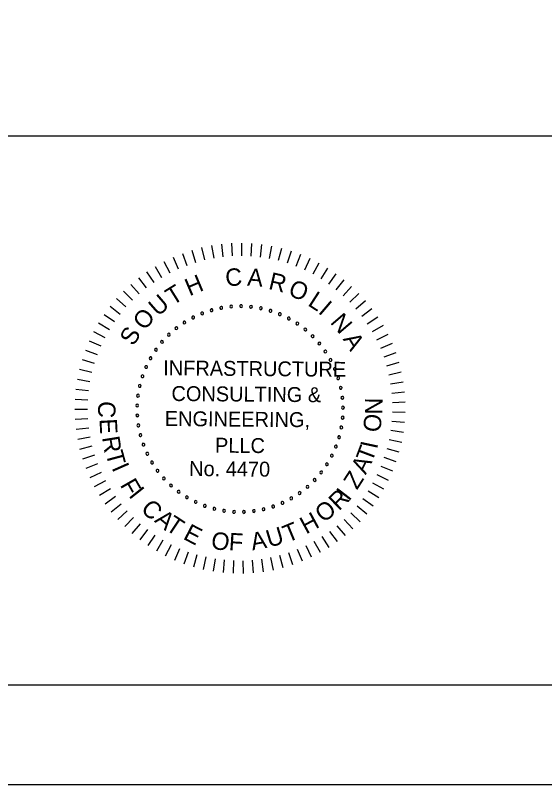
# Model space of a CAD drawing. Extents: x -133.1 to -97, y -1.7 to 20.6.
# Drawn here: x -107.934 to -105.282, y -1.691 to 2.163 of the extents above; entities that cross this region are included whole.
import ezdxf

# ---------------------------------------------------------------- set-up
doc = ezdxf.new("R2010")
doc.units = 0
for name, color, linetype in [('BR_BORDER LINES', 7, 'Continuous'), ('BR_TEXT', 7, 'Continuous'), ('Level 31', 7, 'Continuous')]:
    doc.layers.add(name, color=color, linetype=linetype)

msp = doc.modelspace()

# ---------------------------------------------------------------- linework, layer by layer
at = {"layer": 'BR_BORDER LINES'}
for p, q in [((-110.5071, 1.5591), (-105.1419, 1.5591)), ((-131.3076, -1.191), (-97.6416, -1.191))]:
    msp.add_line(p, q, dxfattribs=at)
at = {"layer": 'BR_TEXT'}
for p, q in [((-106.9512, 1.01), (-106.9401, 0.9473)), ((-106.9012, 1.0172), (-106.894, 0.9539)), ((-106.8509, 1.0213), (-106.8476, 0.9578)), ((-106.8005, 1.0224), (-106.801, 0.9587)), ((-106.75, 1.0204), (-106.7544, 0.9569)), ((-106.6998, 1.0153), (-106.7081, 0.9522)), ((-106.65, 1.0071), (-106.6621, 0.9446)), ((-107.0972, 0.9704), (-107.0749, 0.9107)), ((-107.0494, 0.9866), (-107.0308, 0.9257)), ((-107.0007, 0.9998), (-106.9858, 0.9379)), ((-106.6007, 0.996), (-106.6166, 0.9343)), ((-106.5523, 0.9818), (-106.5719, 0.9213)), ((-106.5048, 0.9648), (-106.528, 0.9055)), ((-107.1895, 0.9295), (-107.1601, 0.873)), ((-107.1439, 0.9513), (-107.1181, 0.8932)), ((-106.4584, 0.9448), (-106.4852, 0.8871)), ((-107.2335, 0.9049), (-107.2008, 0.8503)), ((-106.4133, 0.9221), (-106.4436, 0.8661)), ((-106.3697, 0.8967), (-106.4034, 0.8426)), ((-107.276, 0.8776), (-107.24, 0.8251)), ((-106.3277, 0.8686), (-106.3646, 0.8167)), ((-107.3557, 0.8156), (-107.3135, 0.7679)), ((-107.3168, 0.8478), (-107.2776, 0.7976)), ((-106.2875, 0.8381), (-106.3275, 0.7885)), ((-107.3925, 0.7811), (-107.3475, 0.736)), ((-106.2493, 0.8051), (-106.2922, 0.7581)), ((-107.4272, 0.7444), (-107.3795, 0.7022)), ((-106.2131, 0.7699), (-106.2588, 0.7256)), ((-106.1791, 0.7326), (-106.2275, 0.6911)), ((-107.4595, 0.7056), (-107.4094, 0.6664)), ((-107.4895, 0.665), (-107.437, 0.6289)), ((-106.1475, 0.6932), (-106.1983, 0.6548)), ((-107.5169, 0.6226), (-107.4623, 0.5897)), ((-106.1184, 0.652), (-106.1714, 0.6167)), ((-107.5416, 0.5786), (-107.4852, 0.5491)), ((-106.0918, 0.6091), (-106.1469, 0.5771)), ((-106.0679, 0.5646), (-106.1248, 0.5361)), ((-107.5637, 0.5332), (-107.5055, 0.5072)), ((-106.0467, 0.5188), (-106.1052, 0.4938)), ((-107.5829, 0.4865), (-107.5233, 0.4641)), ((-106.0283, 0.4718), (-106.0883, 0.4504)), ((-107.5992, 0.4387), (-107.5384, 0.42)), ((-107.6126, 0.3901), (-107.5507, 0.3751)), ((-106.0129, 0.4237), (-106.0741, 0.406)), ((-106.0004, 0.3748), (-106.0625, 0.3608)), ((-107.623, 0.3407), (-107.5604, 0.3295)), ((-105.9909, 0.3252), (-106.0538, 0.3151)), ((-107.6304, 0.2907), (-107.5672, 0.2834)), ((-105.9845, 0.2751), (-106.0479, 0.2689)), ((-107.6348, 0.2404), (-107.5712, 0.237)), ((-105.9811, 0.2247), (-106.0448, 0.2224)), ((-107.636, 0.19), (-107.5723, 0.1904)), ((-105.9809, 0.1743), (-106.0445, 0.1758)), ((-107.6342, 0.1395), (-107.5706, 0.1438)), ((-105.9836, 0.1239), (-106.0471, 0.1292)), ((-107.6293, 0.0893), (-107.5661, 0.0974)), ((-105.9895, 0.0737), (-106.0525, 0.0829)), ((-107.6213, 0.0394), (-107.5588, 0.0514)), ((-107.6103, -0.0099), (-107.5487, 0.0059)), ((-105.9984, 0.024), (-106.0607, 0.0371)), ((-106.0103, -0.025), (-106.0717, -0.0082)), ((-107.5964, -0.0584), (-107.5358, -0.0388)), ((-106.0252, -0.0733), (-106.0855, -0.0527)), ((-107.5795, -0.106), (-107.5202, -0.0828)), ((-106.043, -0.1205), (-106.1019, -0.0963)), ((-107.5597, -0.1524), (-107.5019, -0.1256)), ((-106.0636, -0.1666), (-106.1209, -0.1389)), ((-107.5371, -0.1976), (-107.4811, -0.1673)), ((-106.087, -0.2113), (-106.1426, -0.1802)), ((-107.5119, -0.2413), (-107.4578, -0.2077)), ((-106.1131, -0.2545), (-106.1667, -0.22)), ((-107.484, -0.2834), (-107.4321, -0.2465)), ((-106.1418, -0.2961), (-106.1931, -0.2584)), ((-107.4536, -0.3237), (-107.404, -0.2837)), ((-106.173, -0.3358), (-106.2219, -0.2951)), ((-107.4208, -0.362), (-107.3737, -0.3191)), ((-106.2065, -0.3735), (-106.2529, -0.3299)), ((-107.3857, -0.3983), (-107.3413, -0.3527)), ((-107.3485, -0.4324), (-107.307, -0.3841)), ((-106.2423, -0.4092), (-106.2859, -0.3628)), ((-107.3092, -0.4642), (-107.2708, -0.4135)), ((-106.32, -0.4736), (-106.3576, -0.4222)), ((-106.2801, -0.4426), (-106.3208, -0.3936)), ((-107.2681, -0.4935), (-107.2328, -0.4405)), ((-106.3616, -0.5021), (-106.3961, -0.4485)), ((-107.2253, -0.5203), (-107.1933, -0.4652)), ((-107.1809, -0.5444), (-107.1523, -0.4875)), ((-106.4498, -0.5513), (-106.4774, -0.4939)), ((-106.4049, -0.528), (-106.436, -0.4725)), ((-107.1352, -0.5657), (-107.1101, -0.5072)), ((-107.0882, -0.5842), (-107.0668, -0.5243)), ((-107.0402, -0.5998), (-107.0225, -0.5387)), ((-106.5432, -0.5894), (-106.5637, -0.5291)), ((-106.4959, -0.5718), (-106.52, -0.5128)), ((-106.9913, -0.6125), (-106.9773, -0.5504)), ((-106.9418, -0.6221), (-106.9316, -0.5593)), ((-106.8918, -0.6288), (-106.8854, -0.5654)), ((-106.8414, -0.6323), (-106.8389, -0.5687)), ((-106.7909, -0.6328), (-106.7923, -0.5691)), ((-106.7405, -0.6302), (-106.7458, -0.5667)), ((-106.6903, -0.6245), (-106.6995, -0.5615)), ((-106.6406, -0.6158), (-106.6536, -0.5535)), ((-106.5915, -0.6041), (-106.6083, -0.5427))]:
    msp.add_line(p, q, dxfattribs=at)
for centre, start, end in [((-106.9021, 0.6977), 10.6038, 190.6038), ((-106.9021, 0.6977), 190.6038, 10.6038), ((-106.8527, 0.7043), 5.0653, 185.0653), ((-106.8527, 0.7043), 185.0653, 5.0653), ((-106.8029, 0.7062), 359.5268, 179.5268), ((-106.8029, 0.7062), 179.5268, 359.5268), ((-106.7531, 0.7033), 173.9884, 353.9884), ((-106.7531, 0.7033), 353.9884, 173.9884), ((-106.7039, 0.6956), 168.4499, 348.4499), ((-106.7039, 0.6956), 348.4499, 168.4499), ((-107.0431, 0.6496), 27.2191, 207.2191), ((-106.9977, 0.6702), 21.6807, 201.6807), ((-106.9977, 0.6702), 201.6807, 21.6807), ((-106.9506, 0.6862), 16.1422, 196.1422), ((-106.9506, 0.6862), 196.1422, 16.1422), ((-106.6557, 0.6832), 162.9114, 342.9114), ((-106.6557, 0.6832), 342.9114, 162.9114), ((-106.6088, 0.6662), 157.373, 337.373), ((-106.6088, 0.6662), 337.373, 157.373), ((-107.0864, 0.6248), 32.7576, 212.7576), ((-107.0864, 0.6248), 212.7576, 32.7576), ((-107.0431, 0.6496), 207.2191, 27.2191), ((-106.5639, 0.6447), 151.8345, 331.8345), ((-106.5639, 0.6447), 331.8345, 151.8345), ((-106.5212, 0.619), 146.2961, 326.2961), ((-106.5212, 0.619), 326.2961, 146.2961), ((-107.127, 0.5959), 38.2961, 218.2961), ((-107.127, 0.5959), 218.2961, 38.2961), ((-106.4811, 0.5893), 140.7576, 320.7576), ((-106.4811, 0.5893), 320.7576, 140.7576), ((-107.1646, 0.5633), 43.8345, 223.8345), ((-107.1646, 0.5633), 223.8345, 43.8345), ((-106.4442, 0.5559), 135.2191, 315.2191), ((-106.4442, 0.5559), 315.2191, 135.2191), ((-107.1989, 0.5271), 49.373, 229.373), ((-107.1989, 0.5271), 229.373, 49.373), ((-106.4106, 0.5191), 129.6807, 309.6807), ((-106.4106, 0.5191), 309.6807, 129.6807), ((-107.2296, 0.4879), 54.9114, 234.9114), ((-107.2296, 0.4879), 234.9114, 54.9114), ((-106.3808, 0.4792), 124.1422, 304.1422), ((-106.3808, 0.4792), 304.1422, 124.1422), ((-107.2563, 0.4458), 60.4499, 240.4499), ((-107.2563, 0.4458), 240.4499, 60.4499), ((-106.3549, 0.4366), 118.6038, 298.6038), ((-106.3549, 0.4366), 298.6038, 118.6038), ((-107.2788, 0.4014), 65.9884, 245.9884), ((-107.2788, 0.4014), 245.9884, 65.9884), ((-106.3333, 0.3917), 113.0653, 293.0653), ((-106.3333, 0.3917), 293.0653, 113.0653), ((-107.297, 0.3549), 71.5268, 251.5268), ((-107.297, 0.3549), 251.5268, 71.5268), ((-106.3161, 0.3449), 107.5268, 287.5268), ((-106.3161, 0.3449), 287.5268, 107.5268), ((-107.3106, 0.307), 77.0653, 257.0653), ((-107.3106, 0.307), 257.0653, 77.0653), ((-106.3035, 0.2967), 101.9884, 281.9884), ((-106.3035, 0.2967), 281.9884, 101.9884), ((-107.3195, 0.258), 82.6038, 262.6038), ((-107.3195, 0.258), 262.6038, 82.6038), ((-106.2956, 0.2475), 96.4499, 276.4499), ((-106.2956, 0.2475), 276.4499, 96.4499), ((-107.3236, 0.2083), 88.1422, 268.1422), ((-107.3236, 0.2083), 268.1422, 88.1422), ((-106.2925, 0.1977), 90.9114, 270.9114), ((-106.2925, 0.1977), 270.9114, 90.9114), ((-107.3229, 0.1585), 93.6807, 273.6807), ((-107.3229, 0.1585), 273.6807, 93.6807), ((-106.2942, 0.1479), 85.373, 265.373), ((-106.2942, 0.1479), 265.373, 85.373), ((-107.3174, 0.109), 99.2191, 279.2191), ((-107.3174, 0.109), 279.2191, 99.2191), ((-106.3007, 0.0985), 79.8345, 259.8345), ((-106.3007, 0.0985), 259.8345, 79.8345), ((-107.3071, 0.0602), 104.7576, 284.7576), ((-107.3071, 0.0602), 284.7576, 104.7576), ((-106.312, 0.05), 74.2961, 254.2961), ((-106.312, 0.05), 254.2961, 74.2961), ((-107.2922, 0.0126), 110.2961, 290.2961), ((-107.2922, 0.0126), 290.2961, 110.2961), ((-106.3279, 0.0028), 68.7576, 248.7576), ((-106.3279, 0.0028), 248.7576, 68.7576), ((-107.2728, -0.0332), 115.8345, 295.8345), ((-107.2728, -0.0332), 295.8345, 115.8345), ((-106.3483, -0.0427), 63.2191, 243.2191), ((-106.3483, -0.0427), 243.2191, 63.2191), ((-107.249, -0.077), 121.373, 301.373), ((-107.249, -0.077), 301.373, 121.373), ((-107.2211, -0.1183), 126.9114, 306.9114), ((-107.2211, -0.1183), 306.9114, 126.9114), ((-106.3729, -0.086), 57.6807, 237.6807), ((-106.3729, -0.086), 237.6807, 57.6807), ((-107.1894, -0.1567), 132.4499, 312.4499), ((-107.1894, -0.1567), 312.4499, 132.4499), ((-106.4016, -0.1267), 52.1422, 232.1422), ((-106.4016, -0.1267), 232.1422, 52.1422), ((-107.1541, -0.1919), 137.9884, 317.9884), ((-107.1541, -0.1919), 317.9884, 137.9884), ((-106.4702, -0.1989), 41.0653, 221.0653), ((-106.4342, -0.1645), 46.6038, 226.6038), ((-106.4342, -0.1645), 226.6038, 46.6038), ((-107.1156, -0.2235), 143.5268, 323.5268), ((-107.1156, -0.2235), 323.5268, 143.5268), ((-106.5093, -0.2297), 35.5268, 215.5268), ((-106.5093, -0.2297), 215.5268, 35.5268), ((-106.4702, -0.1989), 221.0653, 41.0653), ((-107.0742, -0.2512), 149.0653, 329.0653), ((-107.0742, -0.2512), 329.0653, 149.0653), ((-107.0303, -0.2749), 334.6038, 154.6038), ((-106.5513, -0.2566), 29.9884, 209.9884), ((-106.5513, -0.2566), 209.9884, 29.9884), ((-107.0303, -0.2749), 154.6038, 334.6038), ((-106.9843, -0.2941), 160.1422, 340.1422), ((-106.9843, -0.2941), 340.1422, 160.1422), ((-106.9367, -0.3089), 165.6807, 345.6807), ((-106.9367, -0.3089), 345.6807, 165.6807), ((-106.6899, -0.3114), 13.373, 193.373), ((-106.642, -0.2976), 18.9114, 198.9114), ((-106.642, -0.2976), 198.9114, 18.9114), ((-106.5957, -0.2793), 24.4499, 204.4499), ((-106.5957, -0.2793), 204.4499, 24.4499), ((-106.8879, -0.3189), 171.2191, 351.2191), ((-106.8879, -0.3189), 351.2191, 171.2191), ((-106.8384, -0.3242), 356.7576, 176.7576), ((-106.8384, -0.3242), 176.7576, 356.7576), ((-106.7885, -0.3248), 2.2961, 182.2961), ((-106.7885, -0.3248), 182.2961, 2.2961), ((-106.7389, -0.3205), 7.8345, 187.8345), ((-106.7389, -0.3205), 187.8345, 7.8345), ((-106.6899, -0.3114), 193.373, 13.373)]:
    msp.add_arc(centre, 0.00701, start, end, dxfattribs=at)
at = {"layer": 'Level 31'}
msp.add_lwpolyline([(-133.1409, -1.691), (-97.141, -1.691), (-97.141, 20.309), (-133.1409, 20.309)], close=True, dxfattribs=at)

# ---------------------------------------------------------------- texts
at = {"layer": 'BR_TEXT'}
for s, height, rotation, p in [('C', 0.0872, 4.7281, (-106.8784, 0.8048)), ('A', 0.0872, 355.6981, (-106.7739, 0.8098)), ('H', 0.0872, 22.7882, (-107.0612, 0.7554)), ('R', 0.0872, 346.6681, (-106.6696, 0.7928)), ('T', 0.0872, 31.8182, (-107.1461, 0.7078)), ('O', 0.0872, 337.638, (-106.5719, 0.763)), ('L', 0.0872, 327.108, (-106.4731, 0.7125)), ('U', 0.0872, 40.8482, (-107.2194, 0.6516)), ('I', 0.0872, 319.578, (-106.4205, 0.6747)), ('O', 0.0872, 49.8782, (-107.2864, 0.5806)), ('N', 0.0872, 310.548, (-106.3597, 0.6239)), ('S', 0.0872, 58.9083, (-107.3418, 0.5024)), ('A', 0.0872, 301.5179, (-106.2946, 0.5415)), ('INFRASTRUCTURE', 0.074771, 359.5268, (-107.1932, 0.3599)), ('CONSULTING &', 0.074771, 359.5268, (-107.1519, 0.2313)), ('N', 0.0872, 89.2085, (-106.0953, 0.1628)), ('C', 0.0872, 267.025, (-107.5168, 0.2325)), ('ENGINEERING,', 0.074771, 359.5268, (-107.1855, 0.1059)), ('O', 0.0872, 83.2085, (-106.1064, 0.0713)), ('E', 0.0872, 273.025, (-107.5124, 0.1409)), ('R', 0.0872, 279.025, (-107.4996, 0.0487)), ('PLLC', 0.07477, 359.5268, (-106.9338, -0.0277)), ('T', 0.0872, 69.3954, (-106.1476, -0.0805)), ('I', 0.0872, 77.9093, (-106.1219, -0.013)), ('T', 0.0872, 285.025, (-107.4822, -0.0301)), ('No. 4470', 0.07477, 359.5268, (-107.0633, -0.1446)), ('A', 0.0872, 63.3954, (-106.1784, -0.1408)), ('I', 0.0872, 293.7713, (-107.4525, -0.1032)), ('Z', 0.0872, 57.3954, (-106.2222, -0.2172)), ('F', 0.0872, 299.7713, (-107.4113, -0.1893)), ('I', 0.0872, 308.5268, (-107.3692, -0.2431)), ('R', 0.0872, 44.5268, (-106.3127, -0.3221)), ('I', 0.0872, 52.3339, (-106.2633, -0.2748)), ('C', 0.0872, 314.5268, (-107.3099, -0.3133)), ('O', 0.0872, 38.5268, (-106.3893, -0.3821)), ('A', 0.0872, 320.5268, (-107.2407, -0.3718)), ('T', 0.0872, 326.5268, (-107.1863, -0.4103)), ('H', 0.0872, 28.5268, (-106.4774, -0.4381)), ('E', 0.0872, 332.5268, (-107.0977, -0.4581)), ('T', 0.0872, 22.5268, (-106.5706, -0.4799)), ('A', 0.0872, 10.5268, (-106.7462, -0.5177)), ('U', 0.0872, 16.5268, (-106.6623, -0.5042)), ('O', 0.0872, 350.5268, (-106.9576, -0.507)), ('F', 0.0872, 356.5268, (-106.8661, -0.5161))]:
    msp.add_text(s, height=height, rotation=rotation, dxfattribs=at).set_placement(p)

doc.saveas('drawing.dxf')
